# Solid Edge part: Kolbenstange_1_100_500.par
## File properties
Username: ahadarics
Dokumentum tartalom típus: 0
Author: ahadarics
Last saved by: ahadarics
Revision: 88
Sűrűség: 0,000 kg/m^3
Pontosság: 0,990
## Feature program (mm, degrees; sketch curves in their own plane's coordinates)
base feature "unnamed BaseFeature 1"
thread "unnamed Thread 1"
chamfer "Letörés_1"  SetBackValue2 = 20 deg
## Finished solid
Body 1: solid body, 19 faces, 27 edges, 11 vertices.
  Faces by surface: plane 8, cylinder 5, cone 3, torus 3
  Edges by curve: circle 15, line 7, curve on surface 3, ellipse 2
Bounding box of the edges (mm; curved faces can reach further): 100.000 x 100.000 x 688.500, from (-50, -50, -86.75) to (50, 50, 601.75).
Cylindrical faces by radius (mm): R8.75 x1, R10 x1, R12.25 x1, R12.5 x1, R50 x1
Conical faces (half-angle, radius in mm at the cone's reference point): 20 deg R10 x1, 30 deg R12.375 x1, 60 deg R9.375 x1
Toroidal faces (ring radius, tube radius in mm): R9.15 r0.4 x2, R10.45 r1.8 x1
Planar faces by outward normal: +x 1, +z 3, -x 1, -z 1, oblique 2
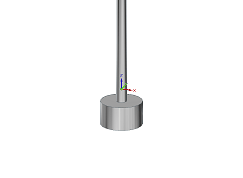
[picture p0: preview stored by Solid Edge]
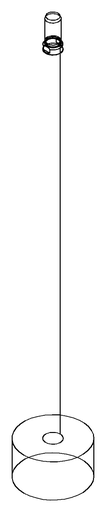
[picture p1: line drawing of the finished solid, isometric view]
